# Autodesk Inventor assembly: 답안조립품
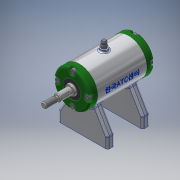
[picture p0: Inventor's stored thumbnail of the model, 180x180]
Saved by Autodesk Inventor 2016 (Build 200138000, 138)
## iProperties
Created: 2018-05
Part Number: 답안조립품
Material: 일반
Document SubType Name: Assembly
Designer: USER
Author: USER
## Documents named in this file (11)
- C:\Users\USER\Desktop\480507v1018\답안조립품.iam
- C:\Users\USER\Desktop\480507v1018\본체.ipt
- C:\Users\USER\Desktop\480507v1018\베어링 6002.ipt
- C:\Users\USER\Desktop\480507v1018\축.ipt
- C:\Users\USER\Desktop\480507v1018\뒤커버.ipt
- C:\Users\USER\Desktop\480507v1018\볼트 M4x12.ipt
- C:\Users\USER\Desktop\480507v1018\앞커버.ipt
- C:\Users\USER\Desktop\480507v1018\오일 실 15 25 7.ipt
- C:\Users\USER\Desktop\480507v1018\니플 M6x0.75.ipt
- C:\Users\USER\Desktop\480507v1018\볼트 M6x8.ipt
- C:\Users\USER\Desktop\480507v1018\와셔 6x11.5.ipt
